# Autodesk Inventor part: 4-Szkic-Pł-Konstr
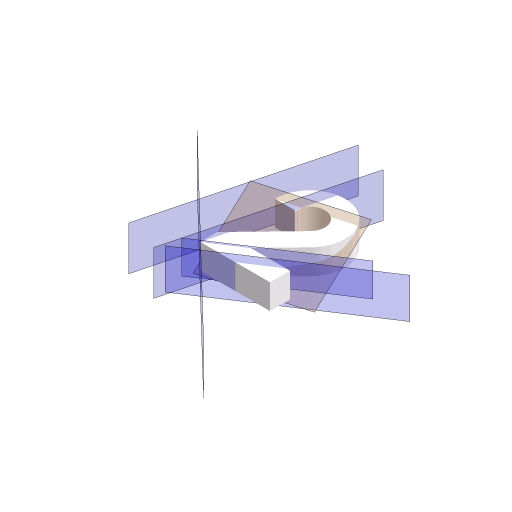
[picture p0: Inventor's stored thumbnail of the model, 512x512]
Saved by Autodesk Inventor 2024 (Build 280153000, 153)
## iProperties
Company: ATC
Shininess: 21.0
Length Units: 11269
Angle Units: 11279
Time Units: 11290
Mass Units: 11283
Length Display Precision: 3
Angle Display Precision: 2
Compacted: True
Created: 2023-03
Part Number: 4-Szkic-Pł-Konstr
Document SubType Name: Modeling
Designer: Andrzej Jaskulski
Material: Kurs-AJ
Density: 1 g/cm^3
Appearance: Kurs-AJ
Checked By: A.J.
Engr Approved By: Andrzej Jaskulski
Mfg Approved By: Andrzej Jaskulski
Authority: A.J.
Density: 0.0
Volumn: 0.0
Area: 0.0
PropertySet Name: Model Information
Control State: 0
Master: False
Checked Out: False
Title: A.J.: Kurs R2024-MEP
Author: Andrzej Jaskulski
Revision Number: 1/24
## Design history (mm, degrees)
sketch "Zarys dwójki"
  geometry: L1 (140, 0.063)-(0, 0.063) reference; L2 (0, 0.063)-(0, 34.389) reference; L3 (0, 150.063)-(40, 150.063); L4 (140, 0.063)-(140, 40.063); L5 (140, 40.063)-(61.086, 40.063); L6 (61.086, 40.063)-(120.354, 101.437); L7 (91.58, 129.223)-(0, 34.389); A1 r 30 centre (70, 150.063) between (91.58, 129.223) and (40, 150.063); A2 r 70 centre (70, 150.063) between (120.354, 101.437) and (0, 150.063)
  constraints: 14 end point, 4 perpendicular, 4 point on circle, 2 centre point, 2 parallel, 2 tangent, 1 coincident
  dimensions: "d0" = 140 distance of L1.start L1.end; "d1" = 150 vertical distance of A1.centre L1.end; "d2" = 70 horizontal distance of L1.end A1.centre; "d3" = 46 deg angle of L6 L5; "d4" = 150 distance of L3.start L1.end (= d1); "d5" = 30 radius of A1; "d6" = 70 radius of A2
extrude "Dwójka" new body sketch "Zarys dwójki" distance "d7" = 50; taper "d8" = 0 deg
node "1 Krawędź i Krawędź"
node "2 Równolegle przez środek krawędzi"
node "3 Krawędź i stycznie do walca"
node "4 Krawędź i prostopadle do ściany"
node "5 Trzy wierzchołki"
node "6 Odsunięta o 70"
node "Bryła1"
node "Korpusy bryłowe"
node "Korpusy powierzchniowe"
other parameters: "d9" = 90 deg, "d10" = 90 deg
